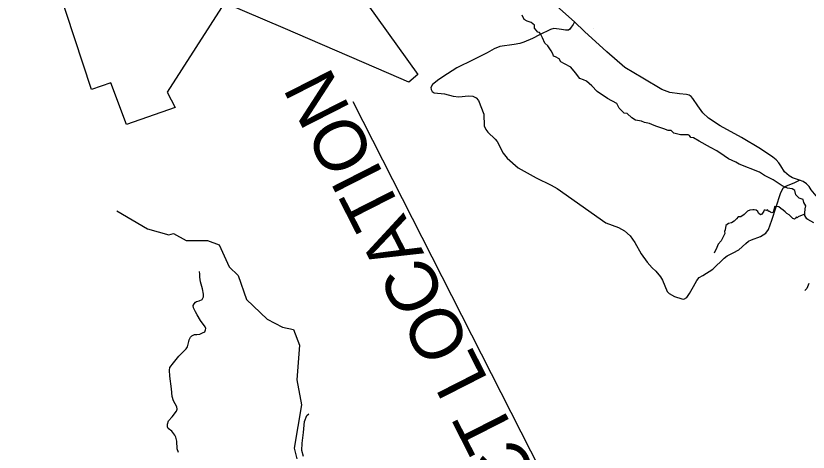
# Model space of a CAD drawing. Extents: x 558484 to 564063, y 513718 to 518374.
# Drawn here: x 559311.7 to 559464.9, y 515017.9 to 515102.2 of the extents above; entities that cross this region are included whole.
import ezdxf

# ---------------------------------------------------------------- set-up
doc = ezdxf.new("R2010")
doc.units = 0
doc.layers.add('Default', color=7, linetype='Continuous')
doc.layers.add('Prop Shade Heavy', color=7, linetype='Continuous')

msp = doc.modelspace()

# ---------------------------------------------------------------- linework, layer by layer
at = {"layer": 'Default'}
msp.add_line((559423.46, 515099.82), (559423.46, 515099.82), dxfattribs=at)
for points in [[(559329.57, 515117.43), (559330.24, 515116.14), (559363.34, 515127.38), (559377.63, 515107.38), (559389.42, 515090.89), (559387.71, 515089.44), (559383.84, 515091.11), (559363.39, 515099.9), (559352.1, 515104.75), (559340.97, 515087.49), (559342.54, 515084.51), (559333.12, 515081.22), (559330.07, 515089.27), (559326.39, 515088), (559318.26, 515112.7), (559311.85, 515116.45), (559311.73, 515116.81)], [(559419.7, 515101.09), (559414.55, 515105.72)], [(559464.27, 515063.89), (559464.26, 515064.13), (559464.32, 515064.91), (559464.45, 515065.54), (559464.07, 515066.15), (559463.92, 515066.72), (559463.14, 515067.03), (559462.51, 515067.67), (559462.31, 515068.49), (559462.12, 515068.62), (559461.78, 515068.8), (559460.9, 515068.92), (559459.86, 515069.39), (559458.15, 515070.57), (559456.45, 515071.4), (559455.48, 515072.01), (559451.54, 515073.54), (559450.9, 515073.96), (559449.49, 515074.58), (559448.66, 515075.16), (559447.25, 515076.13), (559446.01, 515076.8), (559443.83, 515078.02), (559442.71, 515078.68), (559442.19, 515078.75), (559441.95, 515079.09), (559441.7, 515079.23), (559440.21, 515079.25), (559438.92, 515079.59), (559438.4, 515080.09), (559437.86, 515080.06), (559437.01, 515080.41), (559435.67, 515080.82), (559435.16, 515081.03), (559434.26, 515081.4), (559433.24, 515081.65), (559432.68, 515081.88), (559431.52, 515082.06), (559430.8, 515082.53), (559429.94, 515083.35), (559429.36, 515083.41), (559428.37, 515084.4), (559427.94, 515085.29), (559426.14, 515086.26), (559424.13, 515087.63), (559423.06, 515088.69), (559422.05, 515089.58), (559421.46, 515089.88), (559420.76, 515090.13), (559419.94, 515091.22), (559419.04, 515092.29), (559417.82, 515092.97), (559417.11, 515093.35), (559416.74, 515093.89), (559416.08, 515094.29), (559415.66, 515094.45), (559415.6, 515094.77), (559415.24, 515095.48), (559414.6, 515096.44), (559414.02, 515096.94), (559413.52, 515097.95), (559413.14, 515098.74), (559412.97, 515099.04), (559412.63, 515099.1), (559412.02, 515099.82), (559412.01, 515100.42), (559411.34, 515100.93), (559410.56, 515101.19), (559410, 515101.55), (559409.61, 515102.35)], [(559419.7, 515101.09), (559419.47, 515100.56), (559419.11, 515100.04), (559418.84, 515099.66), (559418.58, 515099.49), (559417.99, 515099.49), (559417.24, 515099.6), (559416.75, 515099.64), (559415.72, 515099.77), (559415.06, 515099.62), (559412.96, 515098.58), (559411.6, 515097.87), (559409.95, 515097.16), (559409.16, 515096.9), (559408.08, 515096.71), (559405.27, 515096.31), (559404.19, 515095.85), (559402.86, 515095.07), (559400.15, 515093.71), (559396.98, 515092.18), (559395.21, 515091.05), (559393.52, 515089.94), (559392.29, 515088.97), (559391.95, 515088.41), (559392, 515087.99), (559392.23, 515087.62), (559392.61, 515087.38), (559394.58, 515087.14), (559396.25, 515086.72), (559397.36, 515086.6), (559399.23, 515086.79), (559400.1, 515086.7), (559400.75, 515086.38), (559401.2, 515085.88), (559402.21, 515083.2), (559402.29, 515080.97), (559402.58, 515080.24), (559402.97, 515079.77)], [(559463.26, 515070.45), (559461.88, 515070.9), (559461.2, 515071.31), (559460.35, 515072.09), (559459.64, 515073.22), (559459.22, 515073.85), (559458.73, 515074.42), (559458.08, 515074.93), (559455.71, 515076.52), (559452.04, 515078.75), (559447.91, 515080.98), (559445.66, 515082.44), (559444.53, 515083.48), (559443.55, 515084.87), (559442.59, 515086.27), (559442.28, 515086.62), (559441.92, 515086.88), (559441.38, 515087.05), (559440, 515087.17), (559438.18, 515087.4), (559436.62, 515088), (559432.93, 515090.21), (559429.45, 515092.23), (559425.97, 515095.25), (559421.67, 515099.21), (559419.7, 515101.09)], [(559402.97, 515079.77), (559404.41, 515078.43), (559404.79, 515077.97), (559405.96, 515075.7), (559406.74, 515074.72), (559408.81, 515072.87), (559412.29, 515070.93), (559415.19, 515069.52), (559416.38, 515068.84), (559425.79, 515062.24), (559428.26, 515061.35), (559429.37, 515060.68), (559430.49, 515059.71), (559431.41, 515058.45), (559432.65, 515056.25), (559433.81, 515054.66), (559434.76, 515053.54), (559435.48, 515052.87), (559436.37, 515051.82), (559436.76, 515051.18), (559437.64, 515048.99), (559438.03, 515048.55), (559439.09, 515048.03), (559440.45, 515047.52), (559440.88, 515047.51), (559441.42, 515047.83), (559441.96, 515048.59), (559442.75, 515049.91), (559443.38, 515051.07), (559443.86, 515051.65), (559444.54, 515052.07), (559446.49, 515053.28), (559448.64, 515055.42), (559449.25, 515055.84), (559450.38, 515056.43), (559451.5, 515057), (559452.87, 515058.24), (559453.38, 515058.66), (559453.98, 515058.94), (559455.71, 515059.58), (559456.74, 515060.26), (559457.26, 515060.95), (559457.91, 515062.76), (559459.53, 515067.91), (559460.09, 515068.98), (559460.71, 515069.39), (559462.22, 515069.93), (559463.26, 515070.45)], [(559486.02, 515060.86), (559484.17, 515060.85), (559482.08, 515060.94), (559479.98, 515061.39), (559477.41, 515061.86), (559475.98, 515062.13), (559474.09, 515062.76), (559472.18, 515063.7), (559469.59, 515065.27), (559467.24, 515066.8), (559466.47, 515067.45), (559465.47, 515068.64), (559465.08, 515069.23), (559464.6, 515069.76), (559463.92, 515070.2), (559463.26, 515070.45)], [(559461.92, 515063.07), (559461.48, 515063.5), (559461.25, 515063.79), (559460.78, 515064.04), (559460.43, 515064.37), (559460.06, 515064.68), (559459.63, 515065.01), (559459.22, 515065.34), (559458.37, 515065.39), (559458.3, 515064.96), (559458.26, 515064.78), (559458.16, 515064.3), (559457.89, 515064.16), (559457.6, 515064.32), (559457.45, 515064.4), (559457.22, 515064.41), (559457.14, 515064.6), (559457.06, 515064.72), (559456.91, 515064.69), (559456.82, 515064.62), (559456.57, 515064.66), (559456.39, 515064.66), (559456.31, 515064.51), (559456.2, 515064.31), (559455.93, 515063.9), (559455.66, 515063.8), (559455.27, 515064.1), (559455.15, 515064.41), (559454.88, 515064.66), (559454.49, 515064.72), (559454.18, 515064.74), (559453.62, 515064.7), (559453.2, 515064.47), (559452.54, 515063.83), (559451.88, 515063.38), (559451.35, 515063.38), (559451.06, 515063.01), (559450.59, 515062.58), (559450.06, 515062.25), (559449.53, 515062.09), (559448.98, 515061.71), (559448.88, 515060.86), (559448.71, 515060.56), (559448.78, 515060.18), (559448.39, 515059.42), (559448.11, 515058.78), (559447.48, 515058.09), (559447.24, 515057.48), (559446.72, 515056.37)], [(559331.27, 515064.52), (559337.21, 515061.05), (559341.3, 515059.9), (559342.2, 515060.16), (559344.66, 515058.84), (559348.81, 515058.85), (559351.04, 515058), (559352.95, 515053.72), (559354.7, 515052.08), (559356.34, 515047.4), (559360.33, 515043.63), (559363.29, 515042.1), (559365.4, 515041.62), (559366.58, 515038.59), (559366.05, 515031.93), (559366.93, 515027.04), (559365.55, 515018.72), (559366.04, 515016.65)], [(559464.27, 515063.89), (559463.43, 515063.56), (559463, 515063.38), (559462.79, 515063.21), (559462.57, 515063.32), (559462.49, 515063.21), (559462.48, 515063.04), (559462.26, 515062.95), (559462.13, 515063), (559461.92, 515063.07)], [(559466, 515062.24), (559464.86, 515062.89), (559464.64, 515063.03), (559464.29, 515063.65), (559464.27, 515063.89)], [(559344.91, 515038.26), (559345.2, 515039.32), (559345.27, 515039.63), (559345.5, 515040.12), (559345.77, 515040.41), (559346.27, 515040.63), (559346.75, 515040.66), (559347.31, 515040.73), (559347.81, 515040.96), (559348.25, 515041.2), (559348.42, 515041.53), (559348.47, 515041.84), (559348.34, 515042.17), (559347.44, 515043.38), (559346.76, 515044.44), (559346.45, 515045.01), (559346.08, 515045.78), (559346.04, 515046.28), (559346.21, 515046.58), (559346.45, 515046.88), (559346.67, 515047.03), (559347.18, 515047.18), (559347.74, 515047.42), (559347.98, 515047.91), (559348.04, 515048.42), (559347.81, 515049.45), (559347.46, 515050.83), (559347.33, 515051.76), (559347.31, 515052.33), (559347.23, 515052.84)], [(559465.03, 515050.53), (559464.67, 515049.56), (559464.26, 515049.18)], [(559343.18, 515017.86), (559342.91, 515018.58), (559342.84, 515020.03), (559342.64, 515020.8), (559342.44, 515021.22), (559341.88, 515021.95), (559341.21, 515022.51), (559341.08, 515022.79), (559341.08, 515023.32), (559341.27, 515024), (559341.97, 515024.73), (559342.77, 515025.83), (559342.9, 515026.23), (559342.83, 515026.66), (559342.21, 515027.81), (559341.98, 515028.66), (559341.84, 515030.19), (559341.47, 515032.59), (559341.45, 515033.75), (559341.53, 515034.28), (559342.22, 515035.21), (559343.24, 515036.45), (559344.66, 515037.91), (559344.91, 515038.26)], [(559367.34, 515017.06), (559367.05, 515018.25), (559367.11, 515019.68), (559367.35, 515021.73), (559367.55, 515023.85), (559367.97, 515025), (559368.39, 515025.36)]]:
    msp.add_lwpolyline(points, dxfattribs=at)
at = {"layer": 'Prop Shade Heavy'}
msp.add_line((559435.92, 514969.81), (559376.95, 515085.62), dxfattribs=at)

# ---------------------------------------------------------------- texts
msp.add_text('PROJECT LOCATION', height=10, rotation=116.9819, dxfattribs=at).set_placement((559433.18, 514972.9))

doc.saveas('drawing.dxf')
